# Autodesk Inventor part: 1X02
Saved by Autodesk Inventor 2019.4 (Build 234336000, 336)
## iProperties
Created: 2020-04
Part Number: 1X02
Material: Generic
Document SubType Name: Modeling
Designer: Administrator
Density: 1 g/cm^3
Appearance: Default
Title: 1X02
Author: Administrator
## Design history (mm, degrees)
feature "Body2"
body "Solid1"
